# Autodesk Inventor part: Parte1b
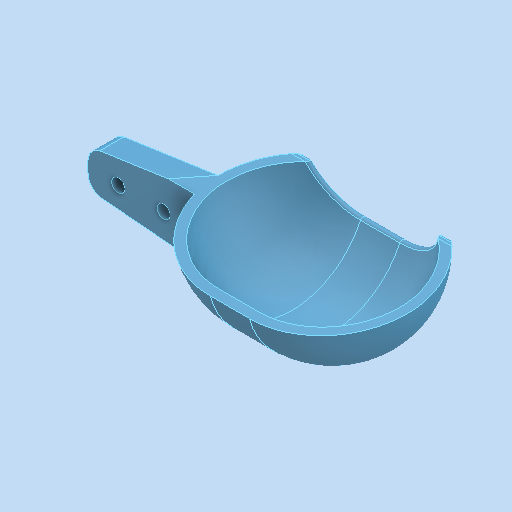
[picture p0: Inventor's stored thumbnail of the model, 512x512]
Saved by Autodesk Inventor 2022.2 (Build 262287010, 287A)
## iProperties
Created: 2025-03
Part Number: Parte1b
Material: Plastica ABS
Document SubType Name: Modeling
Designer: 18907419
Density: 1.06 g/cm^3
Appearance: Default
Author: 18907419
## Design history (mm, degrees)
feature "Solido1"
node "Solido2"
